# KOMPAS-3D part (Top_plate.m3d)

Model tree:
1. X Axis
2. Y Axis
3. Z Axis
4. Origin
     Wall Thickness 1 = 1; Wall Thickness 2 = 1; Distance 1 = 10; Distance 2 = 10

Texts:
  Steel DIN 17102
  Three Point Plane
  Plane at Angle
  Line and Point Plane
  Axis through Two Vertices
  Axis of Feature
  Axis of Conical Surface
  Axis through Edge
  Trim by Surface
  Trim by Sketch
  Feature with No History
  Intersection Axis of Two Planes
  Two Line Plane
  Line and Face Plane
  Bend by line
  Hole in sheet body
  Cut in sheet body
  Point in CM
  Linear Dimension from Line to Point
  Surface Finish Symbol
  Geometric Tolerance Symbol
  Leader #1
  Leader #2
  Leader #3
  Shape Deviations and Datum
  Node point number
  Mark of coordination axis
  Node point designation
  Mark/Reference designation with leader
  Mark/reference designation on line
  Mark/Reference designation without leader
